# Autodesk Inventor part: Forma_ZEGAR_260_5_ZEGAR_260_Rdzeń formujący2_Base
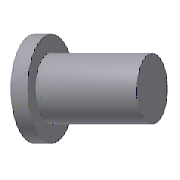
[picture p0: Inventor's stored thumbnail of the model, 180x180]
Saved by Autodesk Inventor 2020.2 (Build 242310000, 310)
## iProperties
Manager: www.cadconsulting.pl
Company: Fabian Stasiak CAD Consulting
Created: 2014-02
Part Number: Forma_ZEGAR_260_5_ZEGAR_260_Rdzeń formujący2_Base
Material: SKD61
Description: Straight Core Pin
Document SubType Name: Modeling
Designer: F.Stasiak
Standard Revision: 1
Manufacturer: PUNCH
Language: pl-PL
Size Designation: 6-60
Categories: <MemberInstance><Categories><Category DisplayName="Forma wtryskowa" InternalName="349578f2-f4d4-4954-8c09-8e99297a61c0" Mnemonic="MOLD"><Category DisplayName="W
Mass: 1.61494 g
Surface Area: 11.4822 cm^2
Volume: 1.61494 cm^3
Density: 7.8 g/cm^3
Appearance: Aluminium - ciemne
Catalog Web Link: www.expertbooks.pl
IsCustomPart: 1
Author: F.Stasiak
Subject: Zbiór ćwiczeń. Autodesk Inventor 2020. Kurs Professional
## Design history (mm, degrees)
sketch "Sketch1"
  geometry: L1 (4.5, 0)-(4.5, 4); L2 (4.5, 4)-(3, 4); L3 (3, 4)-(3, 60); L4 (3, 60)-(0, 60); L5 (4.5, 0)-(0, 0); L6 (0, 0)-(0, 60); L7 (0, 60)-(0, -10) reference; 1 further point
  constraints: 14 end point, 2 horizontal, 1 coincident, 1 collinear, 1 parallel
  dimensions: "d2" = 4 distance of L1.start L1.end (= T_); "d19" = 60 distance between parallel lines of L4 L5 (= L); "d38" = 6 diameter of L3 L7 (= P); "d39" = 9 diameter of L1 L7 (= H_)
revolve "Revolution1" sketch "Sketch1" stored, may be unused: angle "d4" = 90 deg
fillet "Fillet1" dims "d36" = 0.3
workplane "Work Plane1"
sketch "Sketch2"
  geometry: 2 further points
  constraints: 1 vertical alignment
  dimensions: "d21" = 2 distance of point (0, -2) point (0, 0) (= 0.5 x T_)
hole "Anti_Rotary Hole" sketch "Sketch2" at (0, 0) diameter "d22" = 0.8 (= Anti_Rotary_D); stored, may be unused: countersink angle "d26" = 90 deg, drill point angle "d28" = 118 deg; dims "d23" = 6, "d24" = 4, "d25" = 2, "d27" = 1.2 (= 1.5 x Anti_Rotary_D)
sketch "Sketch3"
  geometry: L1 (-3.3, 3.059)-(-3.3, -3.059); A1 r 4.5 centre (0, 0) between (-3.3, 3.059) and (-3.3, -3.059) reference; 1 further point
  constraints: 2 end point, 2 point on circle, 1 vertical
  dimensions: "d29" = 3.3 distance from line of point (0, 0) L1 (= Anti_Rotary_P)
extrude "Anti_Rotary Plane" cut sketch "Sketch3" extent not by distance; stored distance "d30" = 10; taper "d31" = 0 deg
feature "Rzeźbienie1"
body "Solid1"
feature "Powierzchnia1"
body "Srf1"
other parameters: "H_" = 9 [user parameter; used in 1 equation term], "L" = 60 [user parameter; used in 1 equation term], "P" = 6 [user parameter; used in 1 equation term], "d7" = 0, "d8" = 0, "T_" = 4 [user parameter; used in 2 equation terms], "Anti_Rotary_P" = 3.3 [user parameter; used in 1 equation term], "Anti_Rotary_D" = 0.8 [user parameter; used in 2 equation terms], "d32" = 0, "d33" = 0, "d34" = 0, "d35" = 0, "IsARPlane" = 0 [user parameter], "IsARHole" = 0 [user parameter]
